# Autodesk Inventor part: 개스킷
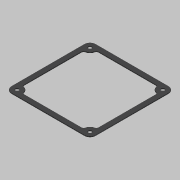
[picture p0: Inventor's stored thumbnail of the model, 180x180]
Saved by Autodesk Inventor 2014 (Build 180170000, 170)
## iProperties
Created: 2019-04
Part Number: 개스킷
Material: 고무
Document SubType Name: Modeling
Designer: mduedu
Density: 0.93 g/cm^3
Appearance: 고무 - 검은색 - 버전 1.1
Mass: 2.32152 g
Surface Area: 58.0824 cm^2
Volume: 2.49626 cm^3
Author: mduedu
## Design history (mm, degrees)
sketch "스케치1"
  geometry: L1 (52.5, 52.5)-(-52.5, 52.5); L2 (-52.5, 52.5)-(-52.5, -52.5); L3 (-52.5, -52.5)-(52.5, -52.5); L4 (52.5, -52.5)-(52.5, 52.5); L5 (52.5, 52.5)-(-52.5, -52.5); L6 (-52.5, 52.5)-(52.5, -52.5); 1 further point
  constraints: 12 end point, 2 midpoint, 2 parallel, 1 horizontal, 1 perpendicular
  dimensions: "d0" = 105 distance of L3.end L2.end; "d1" = 105 distance of L2.end L1.end
extrude "돌출1" new body sketch "스케치1" distance "d2" = 1; taper "d3" = 0 deg
sketch "스케치2"
  geometry: L1 (-52.5, -52.5)-(52.5, -52.5) reference; L2 (52.5, -52.5)-(52.5, 52.5) reference; L3 (52.5, 52.5)-(-52.5, 52.5) reference; L4 (-52.5, 52.5)-(-52.5, -52.5) reference; L5 (-46.5, 46.5)-(46.5, 46.5); L6 (46.5, 46.5)-(46.5, -46.5); L7 (46.5, -46.5)-(-46.5, -46.5); L8 (-46.5, -46.5)-(-46.5, 46.5); 1 further point
  constraints: 8 end point, 3 other
  dimensions: "d4" = 6 distance between parallel lines of L5 L3
extrude "돌출2" cut sketch "스케치2" stored distance "d5" = 1; taper "d6" = 0 deg
fillet "모깎기1" dims "d7" = 7
sketch "스케치3"
  geometry: A1 r 7 centre (-45.5, 45.5) between (-45.5, 52.5) and (-52.5, 45.5) reference; A2 r 7 centre (-45.5, -45.5) between (-52.5, -45.5) and (-45.5, -52.5) reference; A3 r 7 centre (45.5, -45.5) between (45.5, -52.5) and (52.5, -45.5) reference; A4 r 7 centre (45.5, 45.5) between (52.5, 45.5) and (45.5, 52.5) reference; 5 further points
  constraints: 4 coincident, 4 vertical alignment, 8 other
extrude "돌출3" join sketch "스케치3" stored distance "d8" = 1; taper "d9" = 0 deg
fillet "모깎기2" dims "d10" = 3
sketch "스케치4"
  geometry: A1 r 7 centre (-45.5, 45.5) between (-45.5, 52.5) and (-52.5, 45.5) reference; A2 r 7 centre (45.5, 45.5) between (52.5, 45.5) and (45.5, 52.5) reference; A3 r 7 centre (45.5, -45.5) between (45.5, -52.5) and (52.5, -45.5) reference; A4 r 7 centre (-45.5, -45.5) between (-52.5, -45.5) and (-45.5, -52.5) reference; 5 further points
  constraints: 4 coincident
hole "구멍1" sketch "스케치4" at (-45.5, 45.5), (45.5, 45.5), (45.5, -45.5), (-45.5, -45.5) diameter "d11" = 4.5; stored, may be unused: countersink angle "d15" = 90 deg, drill point angle "d17" = 118 deg; dims "d12" = 6, "d13" = 4, "d14" = 2, "d16" = 8
node "솔리드1"
node "투영된 루프1"
